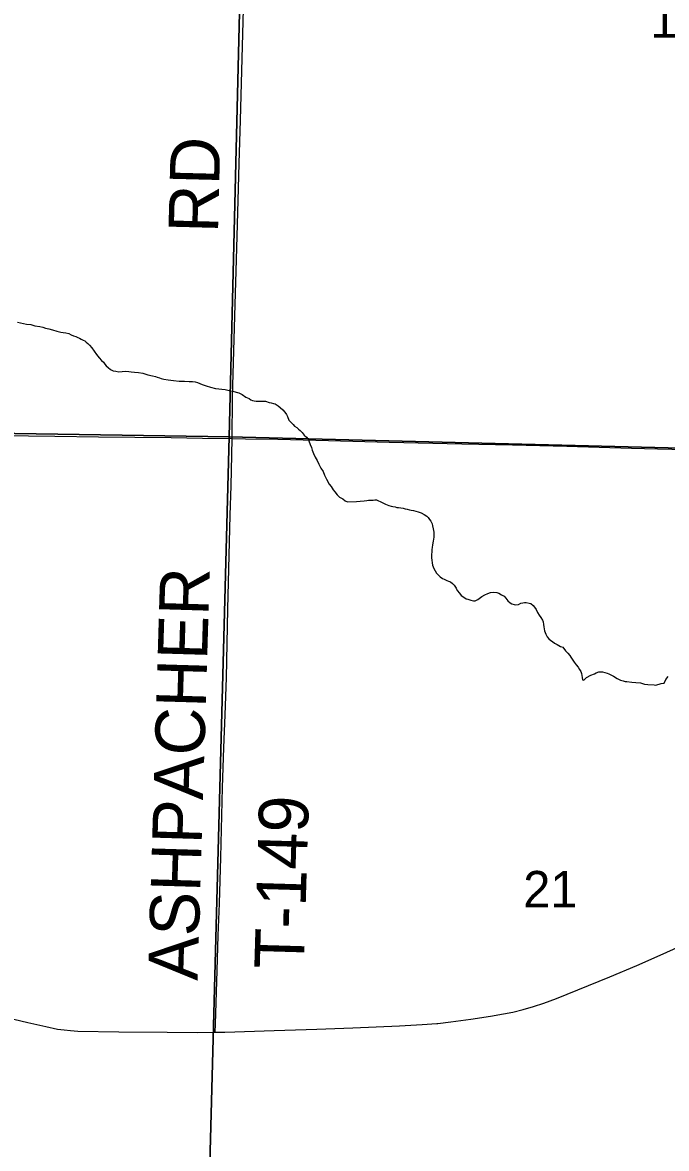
# Model space of a CAD drawing. Extents: x 0 to 34, y 0 to 22.
# Drawn here: x 3.218 to 3.956, y 18.651 to 19.941 of the extents above; entities that cross this region are included whole.
import ezdxf

# ---------------------------------------------------------------- set-up
doc = ezdxf.new("R2010")
doc.units = 0
for name, color, linetype in [('GM_X_Minor_River', 7, 'Continuous'), ('GM_X_Section', 7, 'Continuous'), ('GM_X_Section_Text', 7, 'Continuous'), ('GM_X_Township_Road', 7, 'Continuous'), ('GM_X_Township_Road_Text', 7, 'Continuous')]:
    doc.layers.add(name, color=color, linetype=linetype)

msp = doc.modelspace()

# ---------------------------------------------------------------- linework, layer by layer
at = {"layer": 'GM_X_Minor_River'}
for points in [[(3.2123, 19.598), (3.2225, 19.5955)], [(3.2225, 19.5955), (3.2274, 19.595), (3.2323, 19.5937), (3.238, 19.5928), (3.2414, 19.592), (3.2444, 19.5911), (3.2482, 19.5903), (3.2524, 19.589), (3.2573, 19.5874), (3.2618, 19.5865), (3.2648, 19.5861), (3.2675, 19.5856), (3.2712, 19.5848), (3.2739, 19.5835), (3.2765, 19.5823), (3.2791, 19.5815), (3.2814, 19.5803), (3.2833, 19.5795), (3.2851, 19.5783), (3.2874, 19.5771), (3.2893, 19.5763), (3.2911, 19.5751), (3.293, 19.5736), (3.2948, 19.5716), (3.2974, 19.5685), (3.3, 19.5647), (3.3029, 19.5608), (3.3059, 19.5569), (3.3085, 19.5538), (3.3107, 19.5519), (3.3125, 19.5499), (3.314, 19.548), (3.3162, 19.546), (3.3188, 19.5437), (3.3218, 19.5421), (3.3249, 19.5416), (3.3286, 19.5411), (3.3321, 19.5414), (3.3366, 19.5417), (3.34, 19.5412), (3.3427, 19.5408), (3.3465, 19.5407), (3.351, 19.5402), (3.3559, 19.5393), (3.3616, 19.5376), (3.3669, 19.5364), (3.3703, 19.5355), (3.3725, 19.5347), (3.3752, 19.5339), (3.3771, 19.5335), (3.3801, 19.5326), (3.385, 19.5317), (3.3911, 19.5312), (3.3975, 19.5303), (3.4036, 19.5301), (3.4089, 19.53), (3.4127, 19.5299), (3.4157, 19.5294), (3.4187, 19.5286), (3.424, 19.5266), (3.4285, 19.5249), (3.4334, 19.5233), (3.4391, 19.522), (3.4501, 19.5206), (3.455, 19.5197), (3.4588, 19.5189), (3.4659, 19.5168), (3.4697, 19.5148), (3.4738, 19.512), (3.4779, 19.5104), (3.4798, 19.5088), (3.4817, 19.508), (3.4835, 19.5076), (3.4858, 19.5072), (3.4881, 19.5075), (3.4904, 19.5074), (3.4964, 19.5073), (3.5006, 19.506), (3.5029, 19.5056), (3.5055, 19.5048), (3.5074, 19.5043), (3.5111, 19.502), (3.5134, 19.5), (3.5163, 19.4976), (3.5186, 19.4949), (3.5204, 19.4922), (3.5218, 19.4899), (3.5233, 19.4857), (3.5258, 19.483), (3.5281, 19.4806), (3.5299, 19.4787), (3.5322, 19.4771), (3.5344, 19.4752), (3.5362, 19.4736), (3.5385, 19.4713), (3.5407, 19.4685), (3.5433, 19.4662), (3.5451, 19.4643), (3.5462, 19.462), (3.5476, 19.4577), (3.5491, 19.4543)], [(3.5491, 19.4543), (3.5501, 19.4512), (3.5515, 19.4474), (3.5533, 19.4432), (3.5555, 19.4393), (3.5577, 19.4351), (3.5599, 19.4305), (3.5624, 19.4266), (3.5642, 19.4224), (3.5664, 19.4181), (3.5693, 19.4124), (3.5719, 19.4097), (3.573, 19.4077), (3.574, 19.4058), (3.5759, 19.4035), (3.5785, 19.4), (3.5814, 19.3973), (3.5852, 19.3953), (3.5878, 19.3933), (3.5904, 19.3921), (3.6007, 19.3926), (3.6049, 19.3929), (3.6094, 19.3931), (3.6125, 19.3934), (3.6144, 19.3938), (3.6167, 19.3941), (3.6197, 19.394), (3.6216, 19.3943), (3.6235, 19.3943), (3.6261, 19.3931), (3.628, 19.3923), (3.6303, 19.3911), (3.634, 19.3895), (3.6378, 19.3879), (3.6404, 19.387), (3.6423, 19.3866), (3.645, 19.3862), (3.6469, 19.3857), (3.6488, 19.3857), (3.6514, 19.3852), (3.6541, 19.3848), (3.6567, 19.384), (3.659, 19.3835), (3.6616, 19.3827), (3.6635, 19.3826), (3.6661, 19.3822), (3.6688, 19.3814), (3.6714, 19.3805), (3.6748, 19.3793), (3.6782, 19.3777), (3.6812, 19.3757), (3.683, 19.3742), (3.6845, 19.3719), (3.686, 19.3699), (3.6874, 19.3668), (3.6877, 19.3646), (3.6888, 19.3611), (3.6894, 19.3573), (3.6893, 19.3516), (3.6888, 19.3471), (3.6879, 19.3429), (3.6875, 19.3399), (3.6871, 19.3376), (3.687, 19.335), (3.6869, 19.3312), (3.6868, 19.3277), (3.6877, 19.3194), (3.6892, 19.3155), (3.6924, 19.3105), (3.6965, 19.3062), (3.6995, 19.3043), (3.7014, 19.3035), (3.7044, 19.3019), (3.7063, 19.301), (3.7085, 19.3002), (3.7108, 19.2983), (3.7126, 19.2967), (3.7148, 19.2932), (3.7163, 19.2905), (3.7188, 19.2874), (3.7207, 19.2847), (3.7225, 19.2835), (3.7263, 19.2808), (3.7282, 19.2804), (3.7319, 19.2795), (3.735, 19.2787), (3.7368, 19.2786), (3.7399, 19.2801), (3.7442, 19.2834), (3.7477, 19.2856), (3.7511, 19.287), (3.7542, 19.2881), (3.7572, 19.2887), (3.7614, 19.2883), (3.764, 19.2874), (3.767, 19.2855), (3.77, 19.2839), (3.7719, 19.2815), (3.7741, 19.2788), (3.7767, 19.2765), (3.7789, 19.2753)], [(3.7789, 19.2753), (3.7816, 19.2745), (3.7835, 19.274), (3.7865, 19.2743), (3.7892, 19.2758), (3.7915, 19.2765), (3.7934, 19.2768), (3.7953, 19.2768), (3.7987, 19.2759), (3.8006, 19.2755), (3.8032, 19.2731), (3.8047, 19.2712), (3.8065, 19.2685), (3.8083, 19.2654), (3.8101, 19.2623), (3.812, 19.2596), (3.8138, 19.2566), (3.8145, 19.2546), (3.8152, 19.2516), (3.8155, 19.2489), (3.8161, 19.2443), (3.8176, 19.2405), (3.8194, 19.2374), (3.8212, 19.2351), (3.8235, 19.2331), (3.8253, 19.232), (3.8276, 19.23), (3.8309, 19.2284), (3.8347, 19.2264), (3.8373, 19.2256), (3.8403, 19.2213), (3.8428, 19.2186), (3.8451, 19.2159), (3.8465, 19.2139), (3.8502, 19.2082), (3.8524, 19.2054), (3.8546, 19.2027), (3.8564, 19.2), (3.8579, 19.1977), (3.8586, 19.1954), (3.8592, 19.1908), (3.8596, 19.1882), (3.8614, 19.1877), (3.8642, 19.1907), (3.8692, 19.1936), (3.8734, 19.195), (3.8753, 19.1961), (3.8784, 19.1972), (3.8826, 19.1971), (3.8852, 19.1966), (3.8879, 19.1958), (3.8901, 19.195), (3.8924, 19.1938), (3.8954, 19.1922), (3.8995, 19.1898), (3.9032, 19.1878), (3.9062, 19.187), (3.9085, 19.1862), (3.9104, 19.1861), (3.9161, 19.1856), (3.921, 19.1851), (3.9263, 19.1846), (3.9308, 19.1833), (3.9346, 19.1829), (3.9418, 19.1823), (3.9437, 19.1819), (3.9499, 19.184), (3.9533, 19.1843), (3.9553, 19.1884), (3.958, 19.1921)]]:
    msp.add_lwpolyline(points, dxfattribs=at)
at = {"layer": 'GM_X_Section'}
for points in [[(2.4694, 20.4841), (3.4792, 20.4707), (3.4549, 19.4664), (2.4475, 19.482)], [(3.4792, 20.4707), (4.4862, 20.4566), (4.461, 19.4414), (3.4549, 19.4664)], [(3.4549, 19.4664), (3.4283, 18.4755), (2.4232, 18.4915), (2.4475, 19.482)], [(3.4549, 19.4664), (4.461, 19.4414), (4.4379, 18.4375), (3.4283, 18.4755)]]:
    msp.add_lwpolyline(points, close=True, dxfattribs=at)
at = {"layer": 'GM_X_Township_Road'}
for points in [[(3.4581, 19.4645), (3.4588, 19.5104), (3.4592, 19.5253), (3.4622, 19.631), (3.4629, 19.6564), (3.4643, 19.7099), (3.4655, 19.7515), (3.4663, 19.7795), (3.4677, 19.8292), (3.4713, 19.9566), (3.4728, 20.0115)], [(2.7922, 19.4738), (2.8351, 19.4733), (2.9221, 19.4721), (2.9556, 19.4716), (3.0159, 19.4708), (3.0613, 19.4699), (3.1645, 19.4685), (3.2552, 19.4671), (3.305, 19.4666), (3.3883, 19.4656), (3.4243, 19.4651), (3.4581, 19.4645)], [(3.4389, 18.7843), (3.4392, 18.7937), (3.4412, 18.8553), (3.4423, 18.8951), (3.4437, 18.9317), (3.4453, 18.9846), (3.4473, 19.0647), (3.4489, 19.1101), (3.4502, 19.148), (3.4517, 19.1903), (3.4532, 19.2692), (3.4544, 19.3152), (3.4561, 19.3767), (3.457, 19.4103), (3.4578, 19.4457), (3.4581, 19.4645)], [(3.4581, 19.4645), (3.4734, 19.4643), (3.5107, 19.4638), (3.5685, 19.4624), (3.6381, 19.4604), (3.7214, 19.4586), (3.7797, 19.4572), (3.8419, 19.4557), (3.9158, 19.4536), (3.9457, 19.4529), (4.0283, 19.4507), (4.1576, 19.4477), (4.2576, 19.4453), (4.2974, 19.4446), (4.3546, 19.4431), (4.4049, 19.4419), (4.4312, 19.4412)], [(3.693, 18.7944), (3.694, 18.7945), (3.7088, 18.7964), (3.7316, 18.7994), (3.7544, 18.8028), (3.7691, 18.8053), (3.7801, 18.8075), (3.7916, 18.8104), (3.8036, 18.8138), (3.8154, 18.8177), (3.83, 18.8231), (3.8912, 18.8478), (3.9221, 18.8608), (3.9522, 18.8742), (3.9918, 18.8922), (4.0223, 18.9063), (4.0493, 18.9191), (4.078, 18.9331)], [(3.2079, 18.7995), (3.2242, 18.7955), (3.2449, 18.7908), (3.2583, 18.7881), (3.2657, 18.787), (3.2732, 18.7862), (3.2813, 18.7856), (3.3286, 18.7848), (3.3839, 18.7843), (3.4187, 18.7842), (3.4389, 18.7843)], [(3.4389, 18.7843), (3.4498, 18.7845), (3.5064, 18.7863), (3.5554, 18.7878), (3.5964, 18.7894), (3.6232, 18.7904), (3.6499, 18.7917), (3.676, 18.7931), (3.693, 18.7944)]]:
    msp.add_lwpolyline(points, dxfattribs=at)

# ---------------------------------------------------------------- texts
at = {"layer": 'GM_X_Section_Text'}
for s, p in [('16', (3.9376, 19.9236)), ('21', (3.7918, 18.9273))]:
    msp.add_text(s, height=0.04186, rotation=0, dxfattribs=at).set_placement(p)
at = {"layer": 'GM_X_Township_Road_Text'}
for s, rotation, p in [('RD', 88.5178, (3.442, 19.6996)), ('ASHPACHER', 88.2851, (3.4186, 18.8433)), ('T-149', 88.3145, (3.5404, 18.8562))]:
    msp.add_text(s, height=0.05682, rotation=rotation, dxfattribs=at).set_placement(p)

doc.saveas('drawing.dxf')
